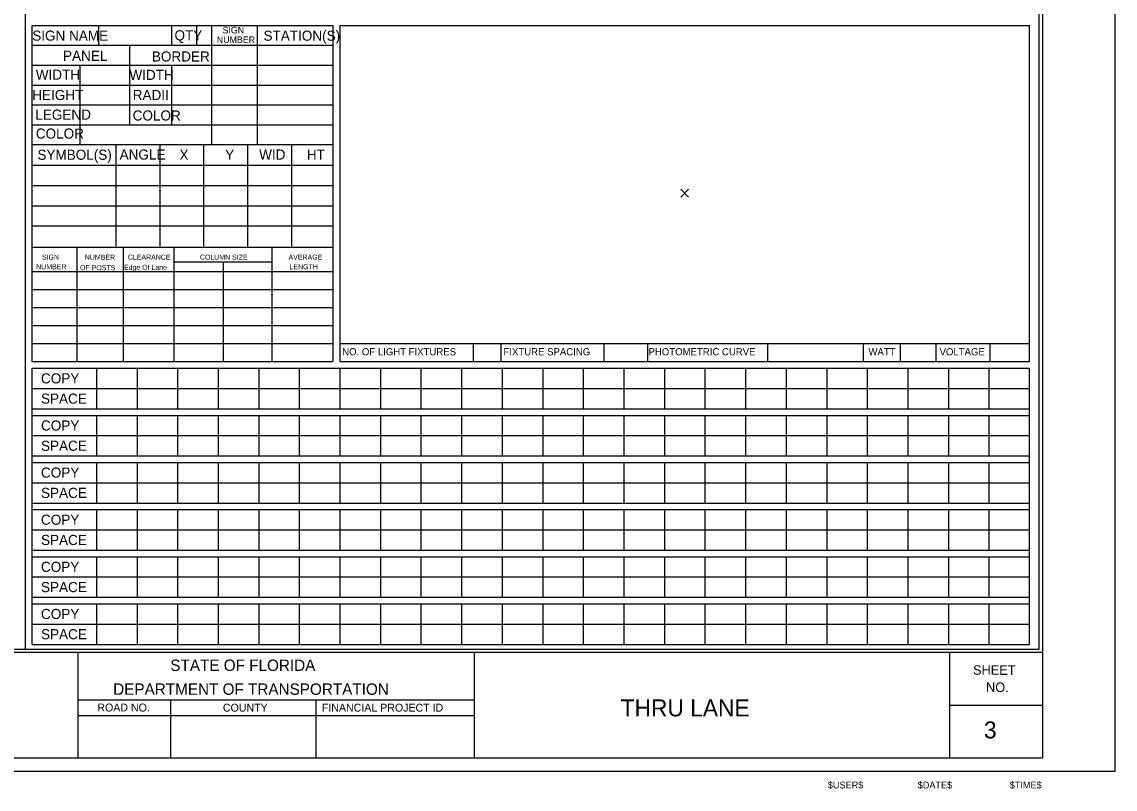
# Model space of a CAD drawing. Extents: x 121688 to 126625, y -22764 to -19972.
# Drawn here: x 125847 to 126625, y -22764 to -22218 of the extents above; entities that cross this region are included whole.
import ezdxf

# ---------------------------------------------------------------- set-up
doc = ezdxf.new("R2010")
doc.units = 0
for name, color, linetype in [('NonPlottingEle_dp', 7, 'Continuous'), ('PlotBorder_dp', 7, 'Continuous'), ('SheetBorder_dp', 7, 'Continuous'), ('SheetLines_dp', 7, 'Continuous'), ('SheetLinesMisc2_dp', 7, 'Continuous'), ('TextMinor', 7, 'Continuous'), ('TextMisc', 7, 'Continuous')]:
    doc.layers.add(name, color=color, linetype=linetype)

msp = doc.modelspace()

# ---------------------------------------------------------------- linework, layer by layer
at = {"layer": 'NonPlottingEle_dp'}
for p, q in [((126315.83, -22337.17), (126321.43, -22342.77)), ((126315.83, -22342.77), (126321.43, -22337.17))]:
    msp.add_line(p, q, dxfattribs=at)
at = {"layer": 'PlotBorder_dp'}
msp.add_lwpolyline([(125072.61, -22751.63), (126625.18, -22751.63), (126625.18, -21754.22), (125072.61, -21754.22)], close=True, dxfattribs=at)
at = {"layer": 'SheetBorder_dp'}
for p, q in [((126573.42, -21763.63), (126573.42, -22742.22)), ((125124.37, -22666.94), (126573.42, -22666.94)), ((125124.37, -22742.22), (126573.42, -22742.22))]:
    msp.add_line(p, q, dxfattribs=at)
at = {"layer": 'SheetLines_dp'}
for p, q in [((125886.53, -22666.94), (125886.53, -22742.22)), ((126168.82, -22742.22), (126168.82, -22666.94)), ((126507.56, -22742.22), (126507.56, -22666.94)), ((125886.53, -22700.82), (126168.82, -22700.82)), ((125952.4, -22700.82), (125952.4, -22742.22)), ((126055.9, -22700.82), (126055.9, -22742.22)), ((126507.56, -22704.58), (126573.42, -22704.58)), ((125886.53, -22712.11), (126168.82, -22712.11))]:
    msp.add_line(p, q, dxfattribs=at)
at = {"layer": 'SheetLinesMisc2_dp'}
for p, q in [((125849.03, -21765.86), (125849.03, -22664.86)), ((126571.14, -22664.87), (126571.14, -21765.86)), ((125853.98, -22459.77), (125853.98, -22220.52)), ((125853.98, -22220.52), (126068.12, -22220.52)), ((125901.19, -22220.52), (125901.19, -22234.65)), ((125953.24, -22220.52), (125953.24, -22234.65)), ((125971.02, -22220.52), (125971.02, -22234.65)), ((125981.62, -22220.52), (125981.62, -22305.31)), ((126014.2, -22220.52), (126014.2, -22305.31)), ((126068.12, -22220.52), (126068.12, -22459.77)), ((126073.04, -22220.52), (126564.23, -22220.52)), ((126073.04, -22220.52), (126073.04, -22459.43)), ((126564.23, -22459.43), (126564.23, -22220.5)), ((125853.98, -22234.65), (126068.12, -22234.65)), ((125923.19, -22234.65), (125923.19, -22291.33)), ((125853.98, -22248.78), (126068.12, -22248.78)), ((125887.82, -22248.78), (125887.82, -22305.31)), ((125953.05, -22248.93), (125953.05, -22291.33)), ((125853.98, -22262.92), (126068.12, -22262.92)), ((125853.98, -22277.05), (126068.12, -22277.05)), ((125853.98, -22291.18), (125933.4, -22291.18)), ((125981.62, -22291.18), (126068.12, -22291.18)), ((125923.19, -22291.33), (125981.62, -22291.33)), ((125853.98, -22305.31), (126068.12, -22305.31)), ((125913.45, -22305.59), (125913.45, -22377.74)), ((125944.74, -22305.59), (125944.74, -22377.74)), ((125976.03, -22305.59), (125976.03, -22377.74)), ((126007.32, -22305.59), (126007.32, -22377.74)), ((126038.61, -22305.59), (126038.61, -22377.74)), ((125854.03, -22320.02), (126068.12, -22320.02)), ((125854.03, -22334.45), (126068.12, -22334.45)), ((125854.03, -22348.88), (126068.12, -22348.88)), ((125854.03, -22363.31), (126068.12, -22363.31)), ((125853.98, -22378.43), (126068.12, -22378.43)), ((125885.76, -22378.43), (125885.76, -22459.77)), ((125918.61, -22378.43), (125918.61, -22459.77)), ((125954.87, -22378.43), (125954.87, -22459.77)), ((126024.7, -22378.43), (126024.7, -22459.77)), ((125954.87, -22388.78), (126024.65, -22388.78)), ((125989.93, -22388.78), (125989.93, -22459.77)), ((125853.98, -22395.68), (126068.12, -22395.68)), ((125853.98, -22408.5), (126068.12, -22408.5)), ((125853.98, -22421.32), (126068.12, -22421.32)), ((125853.98, -22434.14), (126068.12, -22434.14)), ((125853.98, -22446.96), (126068.12, -22446.96)), ((126073.04, -22446.95), (126564.23, -22446.95)), ((126167.92, -22446.95), (126167.92, -22459.77)), ((126187.79, -22446.95), (126187.79, -22459.77)), ((126260.93, -22446.95), (126260.93, -22459.77)), ((126292.06, -22446.95), (126292.06, -22459.77)), ((126377.58, -22446.95), (126377.58, -22459.77)), ((126445.84, -22446.95), (126445.84, -22459.77)), ((126472.19, -22446.95), (126472.19, -22459.77)), ((126497.6, -22446.95), (126497.6, -22459.77)), ((126535.86, -22446.95), (126535.86, -22459.77)), ((125853.98, -22459.77), (126068.12, -22459.77)), ((126073.04, -22459.43), (126073.04, -22459.75)), ((126073.04, -22459.77), (126564.23, -22459.77)), ((126564.23, -22459.75), (126564.23, -22459.43)), ((125853.96, -22464.7), (126564.23, -22464.7)), ((125853.96, -22661.36), (125853.96, -22464.7)), ((125899.69, -22464.7), (125899.69, -22493.55)), ((125928.58, -22464.7), (125928.58, -22493.55)), ((125957.47, -22464.7), (125957.47, -22493.55)), ((125986.36, -22464.7), (125986.36, -22493.55)), ((126015.27, -22464.7), (126015.27, -22493.55)), ((126044.15, -22464.7), (126044.15, -22493.55)), ((126073.04, -22464.7), (126073.04, -22493.55)), ((126101.94, -22464.7), (126101.94, -22493.55)), ((126130.83, -22464.7), (126130.83, -22493.55)), ((126159.73, -22464.7), (126159.73, -22493.55)), ((126188.62, -22464.7), (126188.62, -22493.55)), ((126217.51, -22464.7), (126217.51, -22493.55)), ((126246.41, -22464.7), (126246.41, -22493.55)), ((126275.3, -22464.7), (126275.3, -22493.55)), ((126304.19, -22464.7), (126304.19, -22493.55)), ((126333.08, -22464.7), (126333.08, -22493.55)), ((126361.98, -22464.7), (126361.98, -22493.55)), ((126390.87, -22464.7), (126390.87, -22493.55)), ((126419.76, -22464.7), (126419.76, -22493.55)), ((126448.65, -22464.7), (126448.65, -22493.55)), ((126477.55, -22464.7), (126477.55, -22493.55)), ((126506.45, -22464.7), (126506.45, -22493.55)), ((126535.34, -22464.7), (126535.34, -22493.55)), ((126564.23, -22661.36), (126564.23, -22464.7)), ((125853.96, -22479.12), (126564.23, -22479.12)), ((125853.96, -22493.55), (126564.23, -22493.55)), ((125853.96, -22498.26), (126564.23, -22498.26)), ((125899.69, -22498.26), (125899.69, -22527.12)), ((125928.58, -22498.26), (125928.58, -22527.12)), ((125957.47, -22498.26), (125957.47, -22527.12)), ((125986.36, -22498.26), (125986.36, -22527.12)), ((126015.27, -22498.26), (126015.27, -22527.12)), ((126044.15, -22498.26), (126044.15, -22527.12)), ((126073.04, -22498.26), (126073.04, -22527.12)), ((126101.94, -22498.26), (126101.94, -22527.12)), ((126130.83, -22498.26), (126130.83, -22527.12)), ((126159.73, -22498.26), (126159.73, -22527.12)), ((126188.62, -22498.26), (126188.62, -22527.12)), ((126217.51, -22498.26), (126217.51, -22527.12)), ((126246.41, -22498.26), (126246.41, -22527.12)), ((126275.3, -22498.26), (126275.3, -22527.12)), ((126304.19, -22498.26), (126304.19, -22527.12)), ((126333.08, -22498.26), (126333.08, -22527.12)), ((126361.98, -22498.26), (126361.98, -22527.12)), ((126390.87, -22498.26), (126390.87, -22527.12)), ((126419.76, -22498.26), (126419.76, -22527.12)), ((126448.65, -22498.26), (126448.65, -22527.12)), ((126477.55, -22498.26), (126477.55, -22527.12)), ((126506.45, -22498.26), (126506.45, -22527.12)), ((126535.34, -22498.26), (126535.34, -22527.12)), ((125853.96, -22512.69), (126564.23, -22512.69)), ((125853.96, -22527.12), (126564.23, -22527.12)), ((125853.96, -22531.82), (126564.23, -22531.82)), ((125899.69, -22531.82), (125899.69, -22560.68)), ((125928.58, -22531.82), (125928.58, -22560.68)), ((125957.47, -22531.82), (125957.47, -22560.68)), ((125986.36, -22531.82), (125986.36, -22560.68)), ((126015.27, -22531.82), (126015.27, -22560.68)), ((126044.15, -22531.82), (126044.15, -22560.68)), ((126073.04, -22531.82), (126073.04, -22560.68)), ((126101.94, -22531.82), (126101.94, -22560.68)), ((126130.83, -22531.82), (126130.83, -22560.68)), ((126159.73, -22531.82), (126159.73, -22560.68)), ((126188.62, -22531.82), (126188.62, -22560.68)), ((126217.51, -22531.82), (126217.51, -22560.68)), ((126246.41, -22531.82), (126246.41, -22560.68)), ((126275.3, -22531.82), (126275.3, -22560.68)), ((126304.19, -22531.82), (126304.19, -22560.68)), ((126333.08, -22531.82), (126333.08, -22560.68)), ((126361.98, -22531.82), (126361.98, -22560.68)), ((126390.87, -22531.82), (126390.87, -22560.68)), ((126419.76, -22531.82), (126419.76, -22560.68)), ((126448.65, -22531.82), (126448.65, -22560.68)), ((126477.55, -22531.82), (126477.55, -22560.68)), ((126506.45, -22531.82), (126506.45, -22560.68)), ((126535.34, -22531.82), (126535.34, -22560.68)), ((125853.96, -22546.25), (126564.23, -22546.25)), ((125853.96, -22560.68), (126564.23, -22560.68)), ((125853.96, -22565.38), (126564.23, -22565.38)), ((125899.69, -22565.38), (125899.69, -22594.24)), ((125928.58, -22565.38), (125928.58, -22594.24)), ((125957.47, -22565.38), (125957.47, -22594.24)), ((125986.36, -22565.38), (125986.36, -22594.24)), ((126015.27, -22565.38), (126015.27, -22594.24)), ((126044.15, -22565.38), (126044.15, -22594.24)), ((126073.04, -22565.38), (126073.04, -22594.24)), ((126101.94, -22565.38), (126101.94, -22594.24)), ((126130.83, -22565.38), (126130.83, -22594.24)), ((126159.73, -22565.38), (126159.73, -22594.24)), ((126188.62, -22565.38), (126188.62, -22594.24)), ((126217.51, -22565.38), (126217.51, -22594.24)), ((126246.41, -22565.38), (126246.41, -22594.24)), ((126275.3, -22565.38), (126275.3, -22594.24)), ((126304.19, -22565.38), (126304.19, -22594.24)), ((126333.08, -22565.38), (126333.08, -22594.24)), ((126361.98, -22565.38), (126361.98, -22594.24)), ((126390.87, -22565.38), (126390.87, -22594.24)), ((126419.76, -22565.38), (126419.76, -22594.24)), ((126448.65, -22565.38), (126448.65, -22594.24)), ((126477.55, -22565.38), (126477.55, -22594.24)), ((126506.45, -22565.38), (126506.45, -22594.24)), ((126535.34, -22565.38), (126535.34, -22594.24)), ((125853.96, -22579.8), (126564.23, -22579.8)), ((125853.96, -22594.24), (126564.23, -22594.24)), ((125853.96, -22598.95), (126564.23, -22598.95)), ((125899.69, -22598.95), (125899.69, -22627.8)), ((125928.58, -22598.95), (125928.58, -22627.8)), ((125957.47, -22598.95), (125957.47, -22627.8)), ((125986.36, -22598.95), (125986.36, -22627.8)), ((126015.27, -22598.95), (126015.27, -22627.8)), ((126044.15, -22598.95), (126044.15, -22627.8)), ((126073.04, -22598.95), (126073.04, -22627.8)), ((126101.94, -22598.95), (126101.94, -22627.8)), ((126130.83, -22598.95), (126130.83, -22627.8)), ((126159.73, -22598.95), (126159.73, -22627.8)), ((126188.62, -22598.95), (126188.62, -22627.8)), ((126217.51, -22598.95), (126217.51, -22627.8)), ((126246.41, -22598.95), (126246.41, -22627.8)), ((126275.3, -22598.95), (126275.3, -22627.8)), ((126304.19, -22598.95), (126304.19, -22627.8)), ((126333.08, -22598.95), (126333.08, -22627.8)), ((126361.98, -22598.95), (126361.98, -22627.8)), ((126390.87, -22598.95), (126390.87, -22627.8)), ((126419.76, -22598.95), (126419.76, -22627.8)), ((126448.65, -22598.95), (126448.65, -22627.8)), ((126477.55, -22598.95), (126477.55, -22627.8)), ((126506.45, -22598.95), (126506.45, -22627.8)), ((126535.34, -22598.95), (126535.34, -22627.8)), ((125853.96, -22613.38), (126564.23, -22613.38)), ((125853.96, -22627.8), (126564.23, -22627.8)), ((125853.96, -22632.51), (126564.23, -22632.51)), ((125899.69, -22632.51), (125899.69, -22661.36)), ((125928.58, -22632.51), (125928.58, -22661.36)), ((125957.47, -22632.51), (125957.47, -22661.36)), ((125986.36, -22632.51), (125986.36, -22661.36)), ((126015.27, -22632.51), (126015.27, -22661.36)), ((126044.15, -22632.51), (126044.15, -22661.36)), ((126073.04, -22632.51), (126073.04, -22661.36)), ((126101.94, -22632.51), (126101.94, -22661.36)), ((126130.83, -22632.51), (126130.83, -22661.36)), ((126159.73, -22632.51), (126159.73, -22661.36)), ((126188.62, -22632.51), (126188.62, -22661.36)), ((126217.51, -22632.51), (126217.51, -22661.36)), ((126246.41, -22632.51), (126246.41, -22661.36)), ((126275.3, -22632.51), (126275.3, -22661.36)), ((126304.19, -22632.51), (126304.19, -22661.36)), ((126333.08, -22632.51), (126333.08, -22661.36)), ((126361.98, -22632.51), (126361.98, -22661.36)), ((126390.87, -22632.51), (126390.87, -22661.36)), ((126419.76, -22632.51), (126419.76, -22661.36)), ((126448.65, -22632.51), (126448.65, -22661.36)), ((126477.55, -22632.51), (126477.55, -22661.36)), ((126506.45, -22632.51), (126506.45, -22661.36)), ((126535.34, -22632.51), (126535.34, -22661.36)), ((125853.96, -22646.94), (126564.23, -22646.94)), ((125126.93, -22664.86), (126571.13, -22664.86)), ((125853.96, -22661.36), (126564.23, -22661.36))]:
    msp.add_line(p, q, dxfattribs=at)

# ---------------------------------------------------------------- texts
at = {"layer": 'TextMinor'}
for s, height, p in [('SIGN NAME', 7.199, (125853.98, -22231.34)), ('QTY', 7.199, (125955.29, -22231.1)), ('NUMBER', 4.705, (125985.39, -22233.03)), ('SIGN', 4.705, (125989.48, -22226.18)), ('STATION(S)', 7.199, (126018.69, -22231.38)), ('PANEL', 7.199, (125875.88, -22245.7)), ('BORDER', 7.199, (125939.2, -22246.18)), ('WIDTH', 7.199, (125856.52, -22259.15)), ('WIDTH', 7.199, (125923.19, -22259.29)), ('HEIGHT', 7.199, (125853.98, -22273.63)), ('RADII', 7.199, (125925.55, -22273.61)), ('LEGEND', 7.199, (125856.15, -22287.61)), ('COLOR', 7.199, (125925.5, -22288.22)), ('COLOR', 7.199, (125856.52, -22301.1)), ('SYMBOL(S)', 7.199, (125857.67, -22316.2)), ('ANGLE', 7.199, (125916.2, -22316.05)), ('X', 7.2, (125958.82, -22316.2)), ('Y', 7.2, (125991.35, -22316.2)), ('WID', 7.199, (126015.58, -22316.05)), ('HT', 7.199, (126049.5, -22316.19)), ('SIGN', 3.6, (125860.85, -22387.31)), ('NUMBER', 3.6, (125891.41, -22387.36)), ('CLEARANCE', 3.6, (125922.06, -22387.33)), ('COLUMN SIZE', 3.5997, (125973.36, -22387.33)), ('AVERAGE', 3.6, (126036.5, -22387.33)), ('NUMBER', 3.6, (125856.81, -22394.16)), ('OF POSTS', 3.6, (125888.01, -22394.84)), ('Edge Of Lane', 3.5997, (125919.29, -22394.58)), ('LENGTH', 3.6, (126037.18, -22394.16)), ('NO. OF LIGHT FIXTURES', 5.102, (126074.69, -22455.47)), ('FIXTURE SPACING', 5.102, (126189.56, -22455.47)), ('PHOTOMETRIC CURVE', 5.102, (126292.87, -22455.47)), ('WATT', 5.102, (126449.5, -22455.47)), ('VOLTAGE', 5.102, (126500.15, -22455.47)), ('COPY', 7.199, (125860.21, -22475.48)), ('SPACE', 7.199, (125860.21, -22489.92)), ('COPY', 7.199, (125860.21, -22509.06)), ('SPACE', 7.199, (125860.21, -22523.49)), ('COPY', 7.199, (125860.21, -22542.61)), ('SPACE', 7.199, (125860.21, -22557.04)), ('COPY', 7.199, (125860.21, -22576.18)), ('SPACE', 7.199, (125860.21, -22590.6)), ('COPY', 7.199, (125860.21, -22609.75)), ('SPACE', 7.199, (125860.21, -22624.17)), ('COPY', 7.199, (125860.21, -22643.31)), ('SPACE', 7.199, (125860.21, -22657.73))]:
    msp.add_text(s, height=height, dxfattribs=at).set_placement(p)
at = {"layer": 'TextMisc'}
for s, height, p in [('STATE OF FLORIDA', 8.1298, (125952.3, -22680.33)), ('DEPARTMENT OF TRANSPORTATION', 8.1298, (125911.63, -22697.32)), ('ROAD NO.', 5.646, (125900.36, -22709.19)), ('COUNTY', 5.646, (125989.75, -22709.28)), ('FINANCIAL PROJECT ID', 5.6457, (126060.23, -22709.28)), ('THRU LANE', 12.129, (126272.99, -22712.68)), ('3', 12.13, (126531.74, -22728.39)), ('$USER$', 4.852, (126420.58, -22764.01)), ('$DATE$', 4.852, (126484.59, -22764.01)), ('$TIME$', 4.852, (126550.12, -22764.01))]:
    msp.add_text(s, height=height, dxfattribs=at).set_placement(p)
for s, p in [('SHEET', (126524.02, -22683.03)), ('NO.', (126533.25, -22695.26))]:
    msp.add_text(s, height=6.775, rotation=359.86066, dxfattribs=at).set_placement(p)

doc.saveas('drawing.dxf')
